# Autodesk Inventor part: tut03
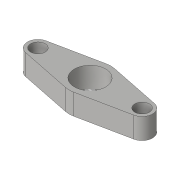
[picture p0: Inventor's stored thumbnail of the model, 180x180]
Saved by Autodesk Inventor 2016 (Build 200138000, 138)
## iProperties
Created: 2015-03
Part Number: tut03
Material: Generic
Document SubType Name: Modeling
Designer: Sandeep
Density: 1 g/cm^3
Appearance: Default
Author: Sandeep
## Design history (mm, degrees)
sketch "Sketch1"
  geometry: L1 (-48.407, 0)-(42.869, 0); L2 (0, 27.195)-(0, -25.865); L3 (-26, 4.899)-(-2, 9.798); L4 (-26, -4.899)-(-2, -9.798); L5 (2, 9.798)-(26, 4.899); L6 (2, -9.798)-(26, -4.899); C1 r 3.5 at (-25, 0); C2 r 3.5 at (25, 0); C3 r 7.5 at (0, 0); A1 r 5 centre (25, 0) between (26, -4.899) and (26, 4.899); A2 r 5 centre (-25, 0) between (-26, 4.899) and (-26, -4.899); A3 r 10 centre (0, 0) between (2, 9.798) and (-2, 9.798); A4 r 10 centre (0, 0) between (-2, -9.798) and (2, -9.798); 1 further point
  constraints: 12 end point, 8 point on circle, 8 tangent, 7 centre point, 4 coincident, 3 equal radius, 3 point on line, 2 equal length, 1 horizontal, 1 vertical, 1 other
  dimensions: "d0" = 10 radius of A3; "d1" = 5 radius of A1; "d2" = 7 diameter of C2; "d3" = 50 distance of A1.centre A2.centre; "d4" = 15 diameter of C3
extrude "Extrusion1" new body sketch "Sketch1" distance "d5" = 10; taper "d6" = 0 deg
body "Solid1"
